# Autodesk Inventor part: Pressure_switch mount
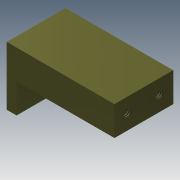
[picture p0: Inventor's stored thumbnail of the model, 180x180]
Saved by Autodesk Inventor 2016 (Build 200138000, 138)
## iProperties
Created: 2014-07
Part Number: Pressure_switch mount
Material: Generic
Document SubType Name: Modeling
Designer: James
Density: 1 g/cm^3
Appearance: Titanium
Author: James
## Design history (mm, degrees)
sketch "Sketch1"
  geometry: L1 (-10.916, 8.367)-(1.084, 8.367); L2 (1.084, 8.367)-(1.084, -3.633); L3 (1.084, -3.633)-(-10.916, -3.633); L4 (-10.916, -3.633)-(-10.916, 8.367); 1 further point
  constraints: 8 end point, 2 parallel, 1 horizontal, 1 perpendicular
  dimensions: "d0" = 12 distance between parallel lines of L2 L4; "d1" = 12 distance between parallel lines of L3 L1
extrude "Extrusion1" new body sketch "Sketch1" distance "d2" = 2; taper "d3" = 0 deg
sketch "Sketch2"
  geometry: L1 (-8.367, 1.084)-(-8.367, -10.916) reference; L2 (-8.367, -10.916)-(3.633, -10.916) reference; L3 (3.633, -10.916)-(3.633, 1.084) reference; L4 (-8.367, 1.084)-(-2.367, 1.084); L5 (-2.367, 1.084)-(-2.367, -10.916); L6 (-2.367, -10.916)-(-8.367, -10.916); L7 (-8.367, -10.916)-(-8.367, 1.084); 2 further points
  constraints: 8 end point, 2 parallel, 1 horizontal, 1 midpoint, 1 perpendicular
  dimensions: "d4" = 6 distance between parallel lines of L5 L7; "d5" = 6 distance from line of L2 point (1.133, -4.916); "d6" = 2.5 distance from line of L3 point (1.133, -4.916)
extrude "Extrusion2" join sketch "Sketch2" distance "d7" = 20; taper "d8" = 0 deg
hole "Hole1" sketch "Sketch2" diameter "d9" = 3.4; stored, may be unused: countersink angle "d13" = 90 deg, drill point angle "d15" = 118 deg; dims "d10" = 6, "d11" = 6.3, "d12" = 2, "d14" = 8
sketch "Sketch4"
  geometry: L1 (22, 12)-(22, 0) reference; L2 (0, 12)-(22, 12) reference; 2 further points
  dimensions: "d16" = 6 distance from line of point (18, 6) L2; "d17" = 4 distance from line of L1 point (18, 6)
hole "Hole2" sketch "Sketch4" at (18, 6) diameter "d18" = 3.4; stored, may be unused: countersink angle "d22" = 90 deg, drill point angle "d24" = 118 deg; dims "d19" = 6, "d20" = 6.3, "d21" = 2, "d23" = 8
sketch "Sketch5"
  geometry: L1 (-8.367, 1.084)-(-8.367, -10.916) reference; L2 (-8.367, -10.916)-(-2.367, -10.916) reference; L3 (-2.367, 1.084)-(-8.367, 1.084) reference; 3 further points
  dimensions: "d25" = 3 distance from line of L1 point (-5.367, -1.666); "d26" = 3 distance from line of L1 point (-5.367, -8.166) (= d25); "d27" = 6.5 distance of point (-5.367, -1.666) point (-5.367, -8.166); "d28" = 2.75 distance from line of L3 point (-5.367, -1.666); "d29" = 2.75 distance from line of L2 point (-5.367, -8.166) (derived)
hole "Hole3" sketch "Sketch5" at (-5.367, -1.666), (-5.367, -8.166) diameter "d30" = 1.567; stored, may be unused: countersink angle "d34" = 82 deg, drill point angle "d36" = 118 deg; dims "d31" = 6, "d32" = 3.023, "d33" = 2, "d35" = 6
body "Solid1"
